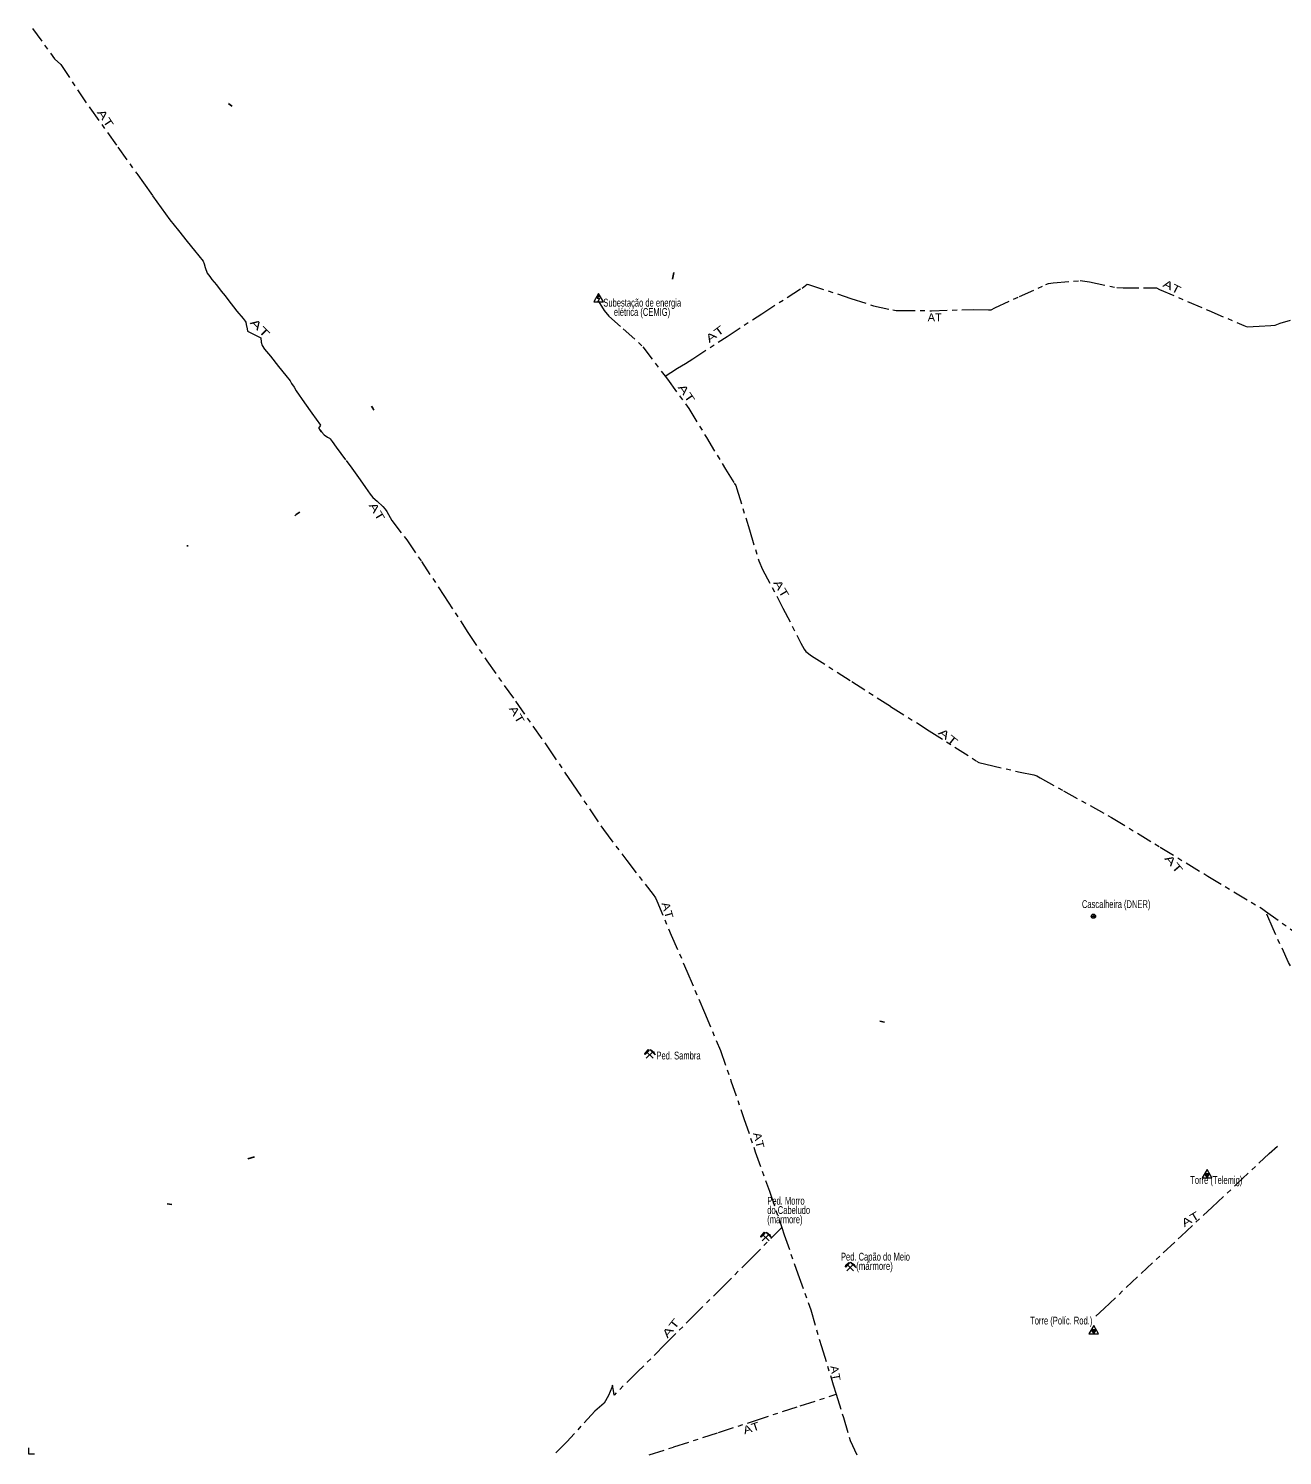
# Model space of a CAD drawing. Extents: x 552.5 to 605.3, y 7843.5 to 7899.1.
# Drawn here: x 552.47 to 578.1, y 7843.69 to 7872.87 of the extents above; entities that cross this region are included whole.
import ezdxf
from ezdxf.enums import TextEntityAlignment as Align

# ---------------------------------------------------------------- set-up
doc = ezdxf.new("R2010")
doc.units = 0
doc.header["$LTSCALE"] = 0.064
doc.header["$PDMODE"] = 32
doc.header["$PDSIZE"] = 0.032
doc.linetypes.add('DOT_DASHED', pattern=[7.7, 5, -1.2, 0.3, -1.2])
for name, color, linetype, lineweight in [('2', 7, 'Continuous', 13), ('24', 7, 'Continuous', 25), ('3', 7, 'Continuous', 13), ('48', 7, 'Continuous', 13), ('56', 7, 'DOT_DASHED', 13), ('63', 7, 'Continuous', 13)]:
    doc.layers.add(name, color=color, linetype=linetype, lineweight=lineweight)
doc.layers.add('61', color=7, linetype='Continuous')

msp = doc.modelspace()

# ---------------------------------------------------------------- hatches: boundary and pattern name
at = {"layer": '2'}
msp.add_hatch(color=256, dxfattribs=at).paths.add_polyline_path([(564.1082, 7867.3976), (564.1342, 7867.4126), (564.1342, 7867.3826)])
at = {"layer": '3'}
for points in [[(576.6139, 7849.448), (576.5139, 7849.448), (576.5639, 7849.362)], [(574.2955, 7846.2578), (574.1955, 7846.2578), (574.2455, 7846.1718)]]:
    msp.add_hatch(color=256, dxfattribs=at).paths.add_polyline_path(points)
at = {"layer": '48'}
for points in [[(565.1363, 7851.9846), (565.1557, 7851.9654), (565.0763, 7851.8862), (565.0725, 7851.8958), (565.0725, 7851.9054), (565.0745, 7851.919), (565.0803, 7851.9286)], [(565.1693, 7851.9886), (565.1865, 7851.9808), (565.2039, 7851.9712), (565.2175, 7851.9634), (565.2291, 7851.9538), (565.2447, 7851.9402), (565.2581, 7851.9208), (565.2659, 7851.9074), (565.2737, 7851.8918), (565.2813, 7851.8764)], [(567.5073, 7848.2493), (567.5267, 7848.2301), (567.4473, 7848.1509), (567.4435, 7848.1605), (567.4435, 7848.1701), (567.4455, 7848.1837), (567.4513, 7848.1933)], [(567.5403, 7848.2533), (567.5575, 7848.2455), (567.5749, 7848.2359), (567.5885, 7848.2281), (567.6001, 7848.2185), (567.6157, 7848.2049), (567.6291, 7848.1855), (567.6369, 7848.1721), (567.6447, 7848.1565), (567.6523, 7848.1411)], [(569.237, 7847.635), (569.2564, 7847.6158), (569.177, 7847.5366), (569.1732, 7847.5462), (569.1732, 7847.5558), (569.1752, 7847.5694), (569.181, 7847.579)], [(569.27, 7847.639), (569.2872, 7847.6312), (569.3046, 7847.6216), (569.3182, 7847.6138), (569.3298, 7847.6042), (569.3454, 7847.5906), (569.3588, 7847.5712), (569.3666, 7847.5578), (569.3744, 7847.5422), (569.382, 7847.5268)]]:
    msp.add_hatch(color=256, dxfattribs=at).paths.add_polyline_path(points)

# ---------------------------------------------------------------- linework, layer by layer
at = {"layer": '2'}
for p, q in [((564.0982, 7867.3506), (564.1212, 7867.3906)), ((564.0982, 7867.3506), (564.1482, 7867.3506)), ((564.1132, 7867.2896), (564.1482, 7867.3506))]:
    msp.add_line(p, q, dxfattribs=at)
for points in [[(564.2242, 7867.2766), (564.1242, 7867.4496), (564.0242, 7867.2766)], [(564.1082, 7867.3976), (564.1342, 7867.4126), (564.1342, 7867.3826)]]:
    msp.add_lwpolyline(points, close=True, dxfattribs=at)
at = {"layer": '24'}
for p, q in [((565.6319, 7867.7421), (565.6626, 7867.8737)), ((555.7169, 7862.2729), (555.7177, 7862.3041)), ((569.8719, 7852.5672), (569.9704, 7852.5488)), ((556.9534, 7849.7493), (557.0922, 7849.7928))]:
    msp.add_line(p, q, dxfattribs=at)
for points in [[(556.555, 7871.3351), (556.6004, 7871.3017), (556.6336, 7871.2773)], [(559.4833, 7865.1428), (559.5059, 7865.1052), (559.5268, 7865.0606)], [(558.4312, 7864.6523), (558.4575, 7864.6197), (558.5116, 7864.5606)], [(557.9121, 7862.9005), (557.9407, 7862.9284), (558.0019, 7862.9692), (558.0135, 7862.9735)], [(555.3076, 7848.8288), (555.3525, 7848.8221), (555.3975, 7848.8154)]]:
    msp.add_lwpolyline(points, dxfattribs=at)
at = {"layer": '3'}
for points in [[(576.6639, 7849.362), (576.5639, 7849.535), (576.4639, 7849.362)], [(576.6139, 7849.448), (576.5139, 7849.448), (576.5639, 7849.362)], [(574.3455, 7846.1718), (574.2455, 7846.3448), (574.1455, 7846.1718)], [(574.2955, 7846.2578), (574.1955, 7846.2578), (574.2455, 7846.1718)]]:
    msp.add_lwpolyline(points, close=True, dxfattribs=at)
at = {"layer": '48'}
for p, q in [((565.0995, 7851.8106), (565.2233, 7851.9344)), ((565.2369, 7851.8106), (565.1189, 7851.9286)), ((567.4705, 7848.0753), (567.5943, 7848.1991)), ((567.6079, 7848.0753), (567.4899, 7848.1933)), ((569.2002, 7847.461), (569.324, 7847.5848)), ((569.3376, 7847.461), (569.2196, 7847.579))]:
    msp.add_line(p, q, dxfattribs=at)
for points in [[(565.1363, 7851.9846), (565.1557, 7851.9654), (565.0763, 7851.8862), (565.0725, 7851.8958), (565.0725, 7851.9054), (565.0745, 7851.919), (565.0803, 7851.9286)], [(565.1693, 7851.9886), (565.1865, 7851.9808), (565.2039, 7851.9712), (565.2175, 7851.9634), (565.2291, 7851.9538), (565.2447, 7851.9402), (565.2581, 7851.9208), (565.2659, 7851.9074), (565.2737, 7851.8918), (565.2813, 7851.8764)], [(567.5073, 7848.2493), (567.5267, 7848.2301), (567.4473, 7848.1509), (567.4435, 7848.1605), (567.4435, 7848.1701), (567.4455, 7848.1837), (567.4513, 7848.1933)], [(567.5403, 7848.2533), (567.5575, 7848.2455), (567.5749, 7848.2359), (567.5885, 7848.2281), (567.6001, 7848.2185), (567.6157, 7848.2049), (567.6291, 7848.1855), (567.6369, 7848.1721), (567.6447, 7848.1565), (567.6523, 7848.1411)], [(569.237, 7847.635), (569.2564, 7847.6158), (569.177, 7847.5366), (569.1732, 7847.5462), (569.1732, 7847.5558), (569.1752, 7847.5694), (569.181, 7847.579)], [(569.27, 7847.639), (569.2872, 7847.6312), (569.3046, 7847.6216), (569.3182, 7847.6138), (569.3298, 7847.6042), (569.3454, 7847.5906), (569.3588, 7847.5712), (569.3666, 7847.5578), (569.3744, 7847.5422), (569.382, 7847.5268)]]:
    msp.add_lwpolyline(points, close=True, dxfattribs=at)
msp.add_circle((574.2402, 7854.7134), 0.043, dxfattribs=at)
msp.add_point((574.2406, 7854.7132), dxfattribs=at)
at = {"layer": '56'}
for points in [[(552.5527, 7872.8656), (553.0008, 7872.2473), (553.1296, 7872.1279), (553.7213, 7871.2421), (554.2951, 7870.443), (554.6769, 7869.9069), (554.6874, 7869.8983), (554.7071, 7869.8749), (554.8178, 7869.7125), (555.0073, 7869.4455), (555.1796, 7869.1982), (555.3555, 7868.9558), (555.5364, 7868.7331), (555.7099, 7868.5128), (555.8637, 7868.3258), (556.0384, 7868.1105), (556.0593, 7868.0551), (556.079, 7867.9813), (556.1246, 7867.8619), (556.1787, 7867.7942), (556.2205, 7867.7364), (556.3116, 7867.622), (556.4088, 7867.4952), (556.4875, 7867.398), (556.5478, 7867.323), (556.7312, 7867.088), (556.8567, 7866.9329), (556.8973, 7866.8825), (556.9096, 7866.8591), (556.9219, 7866.8148), (556.9416, 7866.725), (556.9448, 7866.6787), (557.2221, 7866.544), (557.2246, 7866.4531), (557.2492, 7866.3841), (557.2959, 7866.3079), (557.4202, 7866.1639), (557.5802, 7865.9547), (557.7303, 7865.7714), (557.8201, 7865.6594), (557.8495, 7865.6079), (557.8976, 7865.529), (557.9432, 7865.4576), (558.1142, 7865.2128), (558.2643, 7864.9999), (558.4401, 7864.7564), (558.4207, 7864.7223), (558.3977, 7864.6939), (558.4312, 7864.6523), (558.4575, 7864.6197), (558.5116, 7864.5606), (558.5842, 7864.5126), (558.6199, 7864.4917), (558.6384, 7864.4769), (558.679, 7864.424), (558.7626, 7864.3071), (558.9632, 7864.034), (559.0764, 7863.874), (559.2499, 7863.6353), (559.3557, 7863.4827), (559.4062, 7863.4114), (559.4542, 7863.3437), (559.5071, 7863.2785), (559.5957, 7863.1997), (559.7162, 7863.0951), (559.763, 7863.0398), (559.7966, 7862.9904), (559.8963, 7862.8086), (560.2017, 7862.4113), (560.5021, 7861.9697), (560.9601, 7861.2703), (561.4526, 7860.5152), (561.8384, 7859.9373), (562.4261, 7859.1082), (563.0795, 7858.1758), (563.5885, 7857.4239), (564.2254, 7856.4848), (564.6982, 7855.8561), (565.2383, 7855.16), (565.286, 7855.0927), (565.3122, 7855.0287), (565.6094, 7854.3293), (565.9311, 7853.5873), (566.2874, 7852.7434), (566.6141, 7851.9686), (566.8308, 7851.3447), (567.0967, 7850.5748), (567.3277, 7849.8951), (567.6155, 7849.094), (567.8692, 7848.3467)], [(565.4828, 7865.7539), (565.6025, 7865.8298), (565.74, 7865.9204), (565.9041, 7866.0157), (566.0502, 7866.1137), (566.7496, 7866.569), (567.4597, 7867.0344), (568.2826, 7867.5597), (568.3889, 7867.6406), (568.4187, 7867.631), (569.2828, 7867.3474), (569.7452, 7867.1972), (570.1367, 7867.1129), (570.2042, 7867.0977), (570.2768, 7867.0994), (570.9316, 7867.096), (571.7973, 7867.123), (572.0944, 7867.1146), (572.1484, 7867.1112), (572.2277, 7867.1551), (572.7272, 7867.3846), (573.2673, 7867.6293), (573.323, 7867.6529), (573.4158, 7867.6664), (573.9676, 7867.712), (574.1617, 7867.6833), (574.7153, 7867.5668), (574.8452, 7867.5601), (575.3296, 7867.5635), (575.5287, 7867.5652), (575.5911, 7867.5314), (576.6003, 7867.0977), (577.3142, 7866.7939), (577.3834, 7866.7652), (577.6281, 7866.7804), (577.8644, 7866.7939), (577.9572, 7866.799), (578.0601, 7866.8395), (578.266, 7866.9036)], [(564.114, 7867.2944), (564.2379, 7867.0966), (564.3309, 7866.9815), (564.6276, 7866.7276), (565.0306, 7866.3586), (565.4828, 7865.7539)], [(565.4828, 7865.7539), (565.5295, 7865.6929), (565.9694, 7865.0965), (566.331, 7864.5002), (566.7207, 7863.8537), (566.8949, 7863.5688), (566.9274, 7863.5186), (566.9525, 7863.4522), (567.2063, 7862.6152), (567.3997, 7861.9791), (567.4779, 7861.8064), (567.8927, 7861.0152), (568.2617, 7860.2963), (568.3267, 7860.1723), (568.3577, 7860.1295), (568.4787, 7860.041), (569.2979, 7859.514), (570.095, 7859.0018), (570.8847, 7858.5058), (571.8516, 7857.8874), (571.9003, 7857.8578), (572.0435, 7857.8195), (572.7402, 7857.66), (573.0191, 7857.6025), (573.0826, 7857.5833), (573.1535, 7857.542), (573.6288, 7857.2777), (574.6104, 7856.7316), (575.6067, 7856.1249), (576.5765, 7855.5345), (577.6732, 7854.8747), (577.7575, 7854.8151)], [(578.5884, 7853.1697), (578.2294, 7853.7661), (577.9115, 7854.4584), (577.7575, 7854.8151), (578.5739, 7854.2377)], [(574.286, 7846.538), (574.4584, 7846.6927), (575.2151, 7847.4071), (576.0309, 7848.1689), (576.6677, 7848.7668), (577.1727, 7849.2381), (577.8331, 7849.8579), (578.0055, 7850.0092)], [(567.8692, 7848.3467), (567.2757, 7847.7511), (566.6978, 7847.1716), (566.1396, 7846.6167), (565.4862, 7845.96), (564.9281, 7845.4018), (564.4399, 7844.9212), (564.4293, 7845.0123), (564.4112, 7845.1271), (564.3956, 7845.0759), (564.3245, 7844.9137), (564.2397, 7844.7528), (564.0465, 7844.5926), (563.4752, 7843.9654), (563.2224, 7843.7092)], [(567.8692, 7848.3467), (567.9192, 7848.1993), (568.1967, 7847.4014), (568.461, 7846.661), (568.681, 7845.9124), (568.9223, 7845.1277), (568.9809, 7844.9382)], [(565.1595, 7843.7024), (565.6635, 7843.8603), (566.578, 7844.1558), (567.2937, 7844.3906), (568.2443, 7844.7025), (568.9809, 7844.9382)], [(568.9809, 7844.9382), (569.1285, 7844.4616), (569.2687, 7843.99), (569.4115, 7843.6864)]]:
    msp.add_lwpolyline(points, dxfattribs=at)
at = {"layer": '63'}
msp.add_lwpolyline([(552.4705, 7843.8432), (552.4705, 7843.72), (552.5919, 7843.72)], dxfattribs=at)

# ---------------------------------------------------------------- texts
at = {"layer": '61'}
for rotation, width, p in [(303.69, 1.45, (553.97522, 7870.98418)), (333.173, 1.35, (575.80945, 7867.51203)), (315, 1.65, (557.14538, 7866.68372)), (36.87, 1.5, (566.5499, 7866.55245)), (304.695, 1.5, (565.85325, 7865.35944)), (301.265, 1.45, (559.52298, 7862.94647)), (300.964, 1.4, (567.7891, 7861.36706)), (300.964, 1.4, (562.3824, 7858.79516)), (321.34, 1.55, (571.22012, 7858.3164)), (310.601, 1.55, (575.8202, 7855.72791)), (285.945, 1.25, (565.45601, 7854.81363)), (283.57, 1.2, (567.32179, 7850.11407)), (30.969, 1.4, (576.26233, 7848.44992)), (51.34, 1.55, (565.6643, 7846.23692)), (280.305, 1.15, (568.88701, 7845.35646)), (18.435, 1.25, (567.2702, 7844.17153))]:
    msp.add_text('AT', height=0.16, rotation=rotation, dxfattribs=dict(at, width=width)).set_placement(p, align=Align.CENTER)
for s, width, p in [('Subestação de energia', 0.7, (564.2211, 7867.1798)), ('     elétrica (CEMIG)', 0.7, (564.2211, 7866.9898)), ('Cascalheira (DNER)', 0.7, (574.0051, 7854.8807)), ('Ped. Sambra', 0.7, (565.3066, 7851.7845)), ('Torre (Telemig)', 0.7, (576.2193, 7849.2385)), ('Ped. Morro', 0.7, (567.5715, 7848.8148)), ('do Cabeludo', 0.7, (567.5715, 7848.6248)), ('(mármore)', 0.7, (567.5715, 7848.4348)), ('Ped. Capão do Meio', 0.7, (569.0786, 7847.6717)), ('       (mármore)         ', 0.75, (569.0786, 7847.4817))]:
    msp.add_text(s, height=0.16, dxfattribs=dict(at, width=width)).set_placement(p)
at = {"layer": '61', "width": 1.05}
msp.add_text('AT', height=0.16, dxfattribs=at).set_placement((570.99525, 7866.8804), align=Align.CENTER)
at = {"layer": '61', "width": 0.7}
msp.add_text('Torre (Políc. Rod.)', height=0.16, dxfattribs=at).set_placement((574.2179, 7846.3647), align=Align.RIGHT)

doc.saveas('drawing.dxf')
